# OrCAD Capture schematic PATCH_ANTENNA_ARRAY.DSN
size A
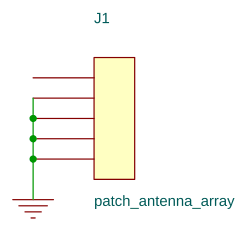
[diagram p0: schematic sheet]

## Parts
J1  patch_antenna_array  [patch_antenna_array]

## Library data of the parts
J1 = CON5

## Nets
GND: J1.2 J1.3 J1.4 J1.5

Not connected (* = marked no-connect by the designer): J1 1
